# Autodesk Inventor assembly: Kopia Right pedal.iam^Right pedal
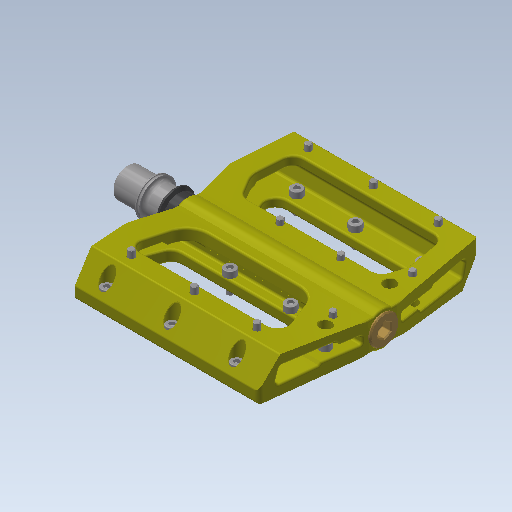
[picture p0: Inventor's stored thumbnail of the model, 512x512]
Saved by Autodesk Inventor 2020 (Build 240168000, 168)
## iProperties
Created: 2017-10
Part Number: Kopia Right pedal.iam^Right pedal
Material: Ogólny
Document SubType Name: Assembly
Designer: Tomasz
Sending System: SolidWorks 2017
Last Author: Tomasz
Last Saved: 2017-11-20
Author: Tomasz
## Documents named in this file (9)
- C:\Users\bruno\Documents\1-Cours-2020-21\1STI2D-2020-21\IT\6. Antivol\Inventor-Antivol\INVENTOR 2018_Steel Hardtail B+\Kopia Right pedal.iam^Right pedal.iam
- C:\Users\bruno\Documents\1-Cours-2020-21\1STI2D-2020-21\IT\6. Antivol\Inventor-Antivol\INVENTOR 2018_Steel Hardtail B+\Kopia full left platform body_MIR.ipt^Kopia Right pedal.iam_Right pedal.ipt
- C:\Users\bruno\Documents\1-Cours-2020-21\1STI2D-2020-21\IT\6. Antivol\Inventor-Antivol\INVENTOR 2018_Steel Hardtail B+\Kopia Axle nut_MIR.ipt^Kopia Right pedal.iam_Right pedal.ipt
- C:\Users\bruno\Documents\1-Cours-2020-21\1STI2D-2020-21\IT\6. Antivol\Inventor-Antivol\INVENTOR 2018_Steel Hardtail B+\Kopia bushing_MIR.ipt^Kopia Right pedal.iam_Right pedal.ipt
- C:\Users\bruno\Documents\1-Cours-2020-21\1STI2D-2020-21\IT\6. Antivol\Inventor-Antivol\INVENTOR 2018_Steel Hardtail B+\Kopia Hex bolt axle cap_MIR.ipt^Kopia Right pedal.iam_Right pedal.ipt
- C:\Users\bruno\Documents\1-Cours-2020-21\1STI2D-2020-21\IT\6. Antivol\Inventor-Antivol\INVENTOR 2018_Steel Hardtail B+\Kopia seal_MIR.ipt^Kopia Right pedal.iam_Right pedal.ipt
- C:\Users\bruno\Documents\1-Cours-2020-21\1STI2D-2020-21\IT\6. Antivol\Inventor-Antivol\INVENTOR 2018_Steel Hardtail B+\Kopia 686-2RS_MIR.iam^Kopia Right pedal.iam_Right pedal.iam
- C:\Users\bruno\Documents\1-Cours-2020-21\1STI2D-2020-21\IT\6. Antivol\Inventor-Antivol\INVENTOR 2018_Steel Hardtail B+\ISO 4762 - M3 x 8DIN EN ISO.ipt
- C:\Users\bruno\Documents\1-Cours-2020-21\1STI2D-2020-21\IT\6. Antivol\Inventor-Antivol\INVENTOR 2018_Steel Hardtail B+\Kopia Right pedal axle.ipt^Kopia Right pedal.iam_Right pedal.ipt
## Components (29 placed, 8 different names)
1. Kopia full left platform body_MIR.ipt^Kopia Right pedal.iam_Right pedal:1
2. Kopia Axle nut_MIR.ipt^Kopia Right pedal.iam_Right pedal:1
3. Kopia bushing_MIR.ipt^Kopia Right pedal.iam_Right pedal:1
4. Kopia Hex bolt axle cap_MIR.ipt^Kopia Right pedal.iam_Right pedal:1
5. Kopia Hex bolt axle cap_MIR.ipt^Kopia Right pedal.iam_Right pedal:2
6. Kopia seal_MIR.ipt^Kopia Right pedal.iam_Right pedal:1
7. Kopia 686-2RS_MIR.iam^Kopia Right pedal.iam_Right pedal:1 [sub-assembly]
8. Kopia 686-2RS_MIR.iam^Kopia Right pedal.iam_Right pedal:2 [sub-assembly]
9. ISO 4762 - M3 x 8DIN EN ISO:21
10. ISO 4762 - M3 x 8DIN EN ISO:2
11. ISO 4762 - M3 x 8DIN EN ISO:3
12. ISO 4762 - M3 x 8DIN EN ISO:4
13. ISO 4762 - M3 x 8DIN EN ISO:5
14. ISO 4762 - M3 x 8DIN EN ISO:6
15. ISO 4762 - M3 x 8DIN EN ISO:7
16. ISO 4762 - M3 x 8DIN EN ISO:8
17. ISO 4762 - M3 x 8DIN EN ISO:9
18. ISO 4762 - M3 x 8DIN EN ISO:10
19. ISO 4762 - M3 x 8DIN EN ISO:11
20. ISO 4762 - M3 x 8DIN EN ISO:12
21. ISO 4762 - M3 x 8DIN EN ISO:13
22. ISO 4762 - M3 x 8DIN EN ISO:14
23. ISO 4762 - M3 x 8DIN EN ISO:15
24. ISO 4762 - M3 x 8DIN EN ISO:16
25. ISO 4762 - M3 x 8DIN EN ISO:17
26. ISO 4762 - M3 x 8DIN EN ISO:18
27. ISO 4762 - M3 x 8DIN EN ISO:19
28. ISO 4762 - M3 x 8DIN EN ISO:20
29. Kopia Right pedal axle.ipt^Kopia Right pedal.iam_Right pedal:1
